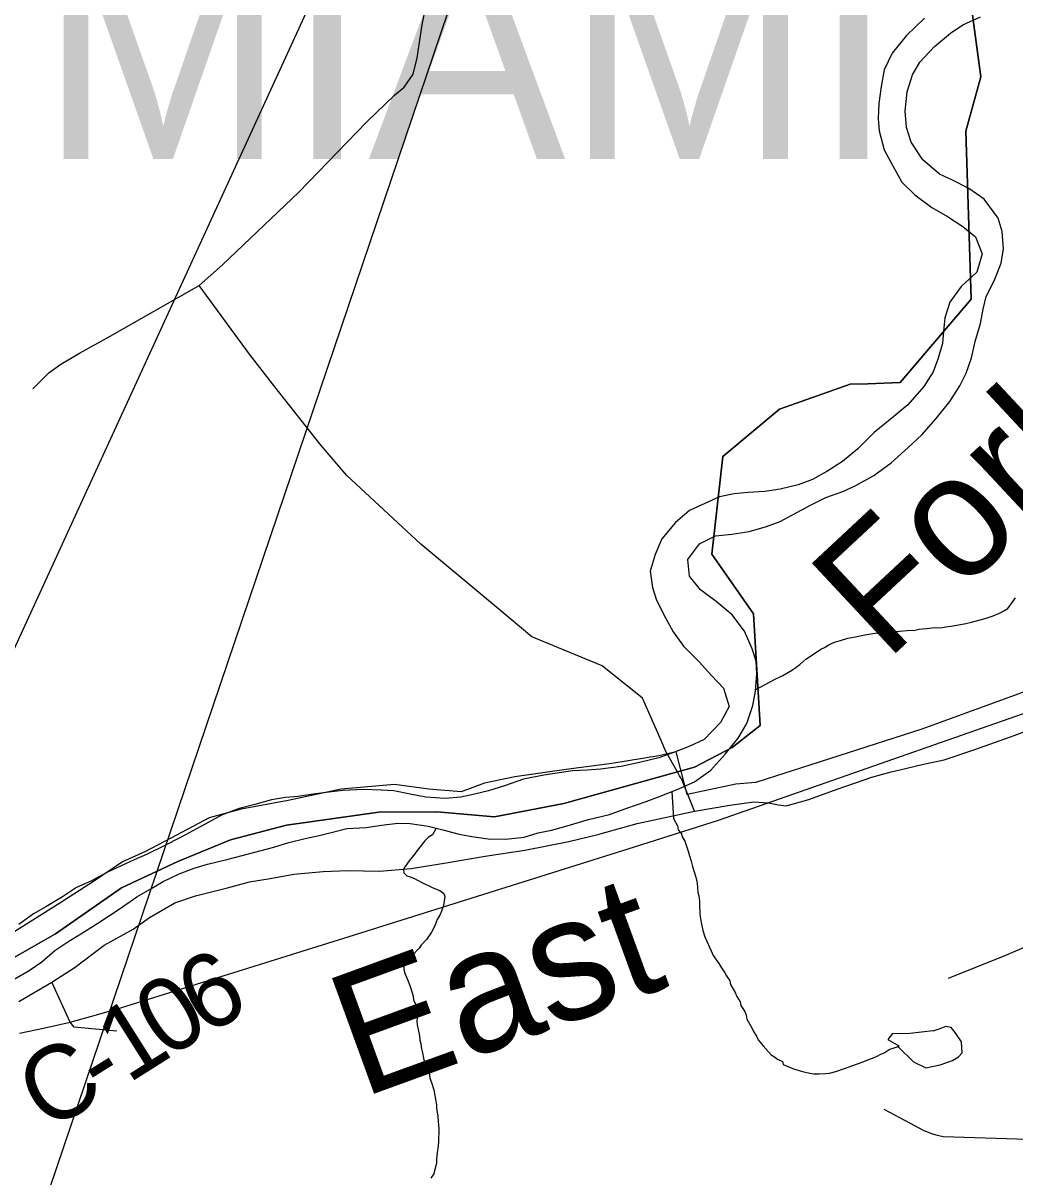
# Model space of a CAD drawing. Extents: x 44.2 to 78.2, y 4.5 to 26.5.
# Drawn here: x 49.072 to 49.836, y 20.266 to 21.155 of the extents above; entities that cross this region are included whole.
import ezdxf

# ---------------------------------------------------------------- set-up
doc = ezdxf.new("R2010")
doc.units = 0
for name, color, linetype in [('GM_X_City_Street', 7, 'Continuous'), ('GM_X_Corporation', 7, 'Continuous'), ('GM_X_County_Road', 7, 'Continuous'), ('GM_X_County_Road_Text', 7, 'Continuous'), ('GM_X_Major_River', 7, 'Continuous'), ('GM_X_Major_River_Text', 7, 'Continuous'), ('GM_X_Minor_Lake', 7, 'Continuous'), ('GM_X_Minor_River', 7, 'Continuous'), ('GM_X_Rail_Line', 7, 'Continuous'), ('GM_X_Township_Road', 7, 'Continuous'), ('GM_X_Township_Text', 7, 'Continuous'), ('SH_Data', 7, 'Continuous')]:
    doc.layers.add(name, color=color, linetype=linetype)

msp = doc.modelspace()

# ---------------------------------------------------------------- linework, layer by layer
at = {"layer": 'GM_X_City_Street'}
msp.add_lwpolyline([(49.07968, 20.87319), (49.09182, 20.88533), (49.10127, 20.89208), (49.11557, 20.90071), (49.13904, 20.91366), (49.20768, 20.95273)], dxfattribs=at)
at = {"layer": 'GM_X_Corporation'}
msp.add_lwpolyline([(49.89099, 20.65721), (49.76414, 20.61103), (49.63643, 20.56998), (49.62086, 20.56872), (49.58355, 20.56061), (49.57505, 20.59345), (49.56153, 20.59035), (49.52539, 20.58465), (49.49021, 20.57989), (49.45074, 20.57428), (49.42744, 20.56943), (49.40936, 20.56277), (49.38464, 20.56467), (49.358, 20.56847), (49.31711, 20.56467), (49.27621, 20.55611), (49.24007, 20.54945), (49.21534, 20.54279), (49.19023, 20.52931), (49.16636, 20.51686), (49.14877, 20.50878), (49.12642, 20.49355), (49.10027, 20.47691), (49.05889, 20.45075)], dxfattribs=at)
at = {"layer": 'GM_X_County_Road'}
for points in [[(49.43689, 20.70467), (49.37826, 20.75352), (49.32135, 20.80634), (49.30173, 20.82953), (49.2659, 20.87471), (49.24633, 20.89981), (49.20768, 20.95273), (49.22569, 20.96854), (49.28439, 21.02463), (49.33646, 21.07856), (49.35812, 21.09941), (49.36563, 21.10533), (49.37237, 21.1155), (49.37567, 21.12815), (49.37938, 21.15358), (49.38172, 21.16499)], [(49.56364, 20.60177), (49.54905, 20.63486), (49.51808, 20.6598), (49.46389, 20.68217), (49.43689, 20.70467)], [(49.58911, 20.54782), (49.61631, 20.5525), (49.63484, 20.55506), (49.64603, 20.55435), (49.6539, 20.55263), (49.65972, 20.55195), (49.67719, 20.55691), (49.69894, 20.56479), (49.72565, 20.57404), (49.74055, 20.57815), (49.75151, 20.58072), (49.76555, 20.58397), (49.78131, 20.5874), (49.80494, 20.59527), (49.83524, 20.60623), (49.89398, 20.62815)], [(49.57768, 20.57515), (49.57631, 20.57761), (49.56688, 20.59441), (49.56364, 20.60177)], [(49.58911, 20.54782), (49.57906, 20.5727), (49.57768, 20.57515)], [(49.06883, 20.40132), (49.09413, 20.41614), (49.1122, 20.4277), (49.13444, 20.44465), (49.15684, 20.45698), (49.16948, 20.46601), (49.189, 20.47722), (49.2049, 20.48264), (49.22948, 20.48878), (49.24646, 20.49348), (49.26237, 20.49601), (49.2805, 20.49926), (49.30328, 20.50146), (49.32185, 20.50223), (49.34664, 20.5016), (49.37096, 20.50363), (49.39799, 20.50796), (49.42801, 20.51309), (49.45856, 20.51774), (49.49238, 20.52439), (49.51475, 20.52998), (49.54492, 20.53829), (49.58911, 20.54782)]]:
    msp.add_lwpolyline(points, dxfattribs=at)
at = {"layer": 'GM_X_Major_River'}
for points in [[(49.80527, 20.90944), (49.80937, 20.92343), (49.81151, 20.93441), (49.81362, 20.94426), (49.81996, 20.9563), (49.82519, 20.96988), (49.82695, 20.98088), (49.8261, 20.9942), (49.82291, 21.00454), (49.81223, 21.01921), (49.80026, 21.02744), (49.78787, 21.03378), (49.77772, 21.03856), (49.76505, 21.04947), (49.75586, 21.06297), (49.75231, 21.07445), (49.75145, 21.08702), (49.75291, 21.10182), (49.757, 21.11505), (49.76253, 21.12482), (49.7738, 21.13676), (49.78617, 21.14715), (49.7958, 21.15342), (49.80922, 21.15961)], [(49.7663, 21.15859), (49.75234, 21.14519), (49.74142, 21.13172), (49.73506, 21.11892), (49.73288, 21.10603), (49.73108, 21.09276), (49.73045, 21.08136), (49.73138, 21.07184), (49.73524, 21.05731), (49.74034, 21.04769), (49.74874, 21.03231), (49.75877, 21.02259), (49.77185, 21.01282), (49.78384, 21.00572), (49.79582, 20.99825), (49.80551, 20.99006), (49.81054, 20.97703), (49.80644, 20.96304), (49.79443, 20.95188), (49.78581, 20.93989), (49.78175, 20.9278), (49.78077, 20.91755), (49.78018, 20.90805), (49.7765, 20.89596), (49.77287, 20.88614), (49.76579, 20.87488), (49.75333, 20.86068), (49.74251, 20.85178), (49.72743, 20.83954), (49.71501, 20.82686), (49.70303, 20.81722), (49.69109, 20.80948), (49.67995, 20.80324), (49.66885, 20.79929), (49.65511, 20.79577), (49.6433, 20.79411), (49.63038, 20.79323), (49.61973, 20.79231), (49.60828, 20.78988), (49.59716, 20.78479), (49.58528, 20.77933), (49.57444, 20.77004), (49.56392, 20.75771), (49.55872, 20.74564), (49.55503, 20.73279), (49.55665, 20.7202), (49.55985, 20.71025), (49.56677, 20.69679), (49.5726, 20.68603), (49.58071, 20.67483), (49.5926, 20.66279), (49.60224, 20.65233), (49.61152, 20.64263), (49.61576, 20.62846), (49.60903, 20.61605), (49.5966, 20.603), (49.58548, 20.5979), (49.57361, 20.5932), (49.56175, 20.58888), (49.54686, 20.58538), (49.53275, 20.58225), (49.51676, 20.5803), (49.50649, 20.57937), (49.49509, 20.57884), (49.473, 20.57549)], [(49.06527, 20.41843), (49.0768, 20.42504), (49.08644, 20.43169), (49.0965, 20.44061), (49.10652, 20.44725), (49.11998, 20.45534), (49.12961, 20.46161), (49.14617, 20.4723), (49.15966, 20.48191), (49.17004, 20.48778), (49.18004, 20.49366), (49.19232, 20.49949), (49.2038, 20.50382), (49.21412, 20.50703), (49.229, 20.51053), (49.24084, 20.51371), (49.26527, 20.52005), (49.27674, 20.52362), (49.28934, 20.52678), (49.30002, 20.52923), (49.31032, 20.53168), (49.3214, 20.53449), (49.33622, 20.53533), (49.34802, 20.53699), (49.36059, 20.53863), (49.37007, 20.53843), (49.38407, 20.53625), (49.39539, 20.53335), (49.40785, 20.53005), (49.41768, 20.52833), (49.43017, 20.52655), (49.44345, 20.52628), (49.45791, 20.52788), (49.46861, 20.53108), (49.47891, 20.53315), (49.48922, 20.53598), (49.50756, 20.54131), (49.52359, 20.54517), (49.53698, 20.55021), (49.5519, 20.55523), (49.56147, 20.55884), (49.57564, 20.56464), (49.58905, 20.57044), (49.60178, 20.57931), (49.61268, 20.59164), (49.62282, 20.60398), (49.62952, 20.61525), (49.634, 20.62923), (49.63614, 20.64022), (49.63719, 20.65351), (49.63664, 20.66341), (49.63344, 20.67298), (49.62766, 20.68641), (49.61807, 20.69916), (49.60576, 20.7093), (49.59381, 20.7183), (49.58531, 20.72874), (49.58407, 20.7417), (49.59307, 20.75368), (49.60535, 20.7599), (49.61791, 20.76116), (49.63124, 20.76317), (49.64461, 20.76708), (49.65495, 20.77105), (49.66455, 20.77618), (49.67838, 20.7835), (49.69027, 20.78934), (49.70328, 20.79401), (49.71287, 20.79838), (49.72709, 20.80646), (49.74059, 20.81607), (49.75375, 20.82797), (49.76422, 20.83764), (49.77512, 20.85035), (49.78566, 20.86344), (49.79351, 20.87545), (49.79828, 20.88524), (49.80234, 20.89695), (49.80527, 20.90944)], [(49.473, 20.57549), (49.45737, 20.57239), (49.44283, 20.56737), (49.4306, 20.56343), (49.41877, 20.56063), (49.40924, 20.55855), (49.39707, 20.55766), (49.38228, 20.55872), (49.37018, 20.56087), (49.35771, 20.56341), (49.34785, 20.564), (49.3342, 20.56466), (49.31824, 20.56384), (49.30758, 20.56254), (49.2954, 20.56089), (49.28397, 20.55922), (49.27408, 20.55828), (49.26342, 20.5566), (49.25043, 20.55307), (49.23859, 20.54989), (49.22482, 20.54485), (49.21521, 20.53934), (49.20292, 20.53275), (49.19331, 20.52762), (49.18064, 20.52103), (49.1676, 20.51483), (49.15763, 20.51047), (49.14766, 20.50574), (49.13654, 20.50064), (49.12425, 20.49404), (49.11313, 20.48895), (49.10234, 20.48194), (49.08965, 20.47422), (49.08004, 20.46871), (49.06885, 20.46057)]]:
    msp.add_lwpolyline(points, dxfattribs=at)
at = {"layer": 'GM_X_Minor_Lake'}
msp.add_lwpolyline([(49.74652, 20.36718), (49.74628, 20.36614), (49.75782, 20.35488), (49.76723, 20.35013), (49.77829, 20.35256), (49.78786, 20.35578), (49.79248, 20.35873), (49.7952, 20.36171), (49.79461, 20.37008), (49.78983, 20.3774), (49.78687, 20.38126), (49.78271, 20.38211), (49.77734, 20.37994), (49.77275, 20.37851)], dxfattribs=at)
at = {"layer": 'GM_X_Minor_River'}
for points in [[(49.63624, 20.64153), (49.6506, 20.64917), (49.65713, 20.65241), (49.66446, 20.65677), (49.67026, 20.66079), (49.67492, 20.66484), (49.67994, 20.66813), (49.68651, 20.67251), (49.68921, 20.67396), (49.69192, 20.67578), (49.6946, 20.67685), (49.69768, 20.67828), (49.7015, 20.67932), (49.70724, 20.68107), (49.71296, 20.68206), (49.72022, 20.68377), (49.72633, 20.68475), (49.73204, 20.68535), (49.73433, 20.68568), (49.74118, 20.68625), (49.74688, 20.68648), (49.75297, 20.68708), (49.75868, 20.68731), (49.76211, 20.68798), (49.76478, 20.68829), (49.7682, 20.68858), (49.77392, 20.68919), (49.77657, 20.68912), (49.78, 20.68941), (49.78267, 20.68972), (49.78648, 20.69038), (49.79106, 20.69102), (49.79793, 20.69236), (49.80251, 20.69338), (49.80519, 20.69407), (49.80901, 20.6951), (49.8136, 20.6965), (49.81897, 20.69826), (49.82396, 20.7004), (49.82742, 20.70221), (49.83051, 20.70403), (49.83247, 20.70663), (49.83641, 20.71222)], [(49.57166, 20.56301), (49.57306, 20.54231), (49.57595, 20.53654), (49.57663, 20.53349), (49.57921, 20.53039), (49.57953, 20.5281), (49.58172, 20.52463), (49.58312, 20.52004), (49.58419, 20.51698), (49.58524, 20.51353), (49.58665, 20.50932), (49.58768, 20.50512), (49.59014, 20.49709), (49.59116, 20.49251), (49.59174, 20.48529), (49.59243, 20.48261), (49.59308, 20.47842), (49.593, 20.47539), (49.59323, 20.46932), (49.59354, 20.46665), (49.59419, 20.46208), (49.59555, 20.45598), (49.59694, 20.45101), (49.60199, 20.44025), (49.60342, 20.4368), (49.60782, 20.43061), (49.60927, 20.42792), (49.61257, 20.42328), (49.61365, 20.42098), (49.61621, 20.41712), (49.6169, 20.41444), (49.62054, 20.40828), (49.6216, 20.40521), (49.62416, 20.40097), (49.62485, 20.3983), (49.62777, 20.39367), (49.62883, 20.39061), (49.62951, 20.38755), (49.63314, 20.38101), (49.63422, 20.37871), (49.63715, 20.37407), (49.63823, 20.37177), (49.64191, 20.36712), (49.64597, 20.36246), (49.64819, 20.36013), (49.65081, 20.35854), (49.65304, 20.35697), (49.65679, 20.35497), (49.65749, 20.35268), (49.6605, 20.35146), (49.66538, 20.34943), (49.67217, 20.34736), (49.67783, 20.34607), (49.68086, 20.34561), (49.68504, 20.34551), (49.69036, 20.34575), (49.69303, 20.34606), (49.698, 20.34744), (49.70451, 20.34955), (49.71831, 20.3545), (49.72253, 20.35629), (49.72752, 20.35805), (49.72982, 20.35913), (49.73252, 20.36058), (49.7352, 20.36165), (49.73907, 20.3642), (49.7452, 20.36632), (49.74652, 20.36718)], [(49.39019, 20.53468), (49.38738, 20.52971), (49.3843, 20.52789), (49.38156, 20.52493), (49.37568, 20.5175), (49.37371, 20.51489), (49.3694, 20.50969), (49.36625, 20.50522), (49.36505, 20.50298), (49.36536, 20.50031), (49.36758, 20.49798), (49.37022, 20.49715), (49.37361, 20.49592), (49.37586, 20.49473), (49.3796, 20.49273), (49.38486, 20.49032), (49.38711, 20.48912), (49.39312, 20.48669), (49.3961, 20.48433), (49.39681, 20.48204), (49.39587, 20.47523), (49.39424, 20.47072), (49.39302, 20.46772), (49.39104, 20.46436), (49.38941, 20.46023), (49.38821, 20.4576), (49.38661, 20.45461), (49.38267, 20.44902), (49.37876, 20.44457), (49.37718, 20.44233), (49.37173, 20.43679), (49.36859, 20.43307), (49.36662, 20.43009), (49.36504, 20.42785), (49.3657, 20.42367), (49.36822, 20.41829), (49.37, 20.41369), (49.3707, 20.41139), (49.37244, 20.40528), (49.37276, 20.40261), (49.37419, 20.39916), (49.37445, 20.3946), (49.37476, 20.39194), (49.37545, 20.38889), (49.37537, 20.38585), (49.37568, 20.38319), (49.37635, 20.37976), (49.37737, 20.3748), (49.37766, 20.37138), (49.37835, 20.3687), (49.37901, 20.36489), (49.3797, 20.36184), (49.38035, 20.35765), (49.38105, 20.35535), (49.38355, 20.34921), (49.38497, 20.34501), (49.38528, 20.34234), (49.38671, 20.33889), (49.38846, 20.33315), (49.38911, 20.32896), (49.39045, 20.32172), (49.39038, 20.31907), (49.39136, 20.31259), (49.39164, 20.30879), (49.39226, 20.30308), (49.39199, 20.29285), (49.39149, 20.28793), (49.39103, 20.2849), (49.39052, 20.2796), (49.39045, 20.27695), (49.38961, 20.27356), (49.38878, 20.27092), (49.38834, 20.26866), (49.38598, 20.26531)], [(49.77287, 20.37855), (49.75486, 20.3766), (49.74725, 20.37638), (49.74156, 20.3765), (49.73804, 20.37201), (49.74652, 20.36718)]]:
    msp.add_lwpolyline(points, dxfattribs=at)
at = {"layer": 'GM_X_Rail_Line'}
for points in [[(49.05006, 20.42655), (49.09709, 20.45325), (49.14794, 20.48884), (49.19115, 20.50919), (49.23183, 20.52572), (49.27504, 20.53716), (49.3461, 20.54699), (49.39071, 20.54733), (49.4352, 20.54351), (49.48858, 20.55368), (49.57607, 20.57813), (49.589, 20.58165), (49.61824, 20.59691), (49.6398, 20.61391), (49.63459, 20.69971), (49.60243, 20.74586), (49.611, 20.82094), (49.65451, 20.85743), (49.7091, 20.87663), (49.72257, 20.87707), (49.74742, 20.87787), (49.80206, 20.94229), (49.79795, 21.07153), (49.80971, 21.1135), (49.80302, 21.16301)], [(49.80302, 21.16301), (49.80971, 21.1135), (49.79795, 21.07153), (49.80206, 20.94229), (49.74742, 20.87787), (49.72257, 20.87707), (49.7091, 20.87663), (49.65451, 20.85743), (49.611, 20.82094), (49.60243, 20.74586), (49.63459, 20.69971), (49.6398, 20.61391), (49.61824, 20.59691), (49.589, 20.58165), (49.57607, 20.57813), (49.48858, 20.55368), (49.4352, 20.54351), (49.39071, 20.54733), (49.3461, 20.54699), (49.27504, 20.53716), (49.23183, 20.52572), (49.19115, 20.50919), (49.14794, 20.48884), (49.09709, 20.45325), (49.05006, 20.42655)], [(49.06921, 20.37698), (49.08777, 20.38063), (49.10823, 20.38539), (49.12393, 20.38967), (49.14471, 20.3957), (49.32311, 20.45136), (49.54299, 20.5203), (49.60769, 20.54082), (49.9144, 20.64833)]]:
    msp.add_lwpolyline(points, dxfattribs=at)
at = {"layer": 'GM_X_Township_Road'}
for points in [[(49.84474, 20.44367), (49.82854, 20.43677), (49.78432, 20.41886)], [(49.1444, 20.37839), (49.11137, 20.38157), (49.10827, 20.38529), (49.09413, 20.41614)], [(49.73483, 20.3183), (49.75513, 20.30765), (49.76528, 20.30208), (49.77072, 20.29998), (49.77505, 20.29862), (49.78062, 20.29738), (49.84561, 20.29515), (49.89351, 20.29383), (49.91195, 20.29314)]]:
    msp.add_lwpolyline(points, dxfattribs=at)
at = {"layer": 'SH_Data'}
msp.add_lwpolyline([(49.00464, 20.54121), (49.70559, 22.06866), (49.00464, 19.99878)], close=True, dxfattribs=at)

# ---------------------------------------------------------------- texts
at = {"layer": 'GM_X_County_Road_Text'}
for s, rotation, p in [('6', 28.00575, (49.21114, 20.37461)), ('0', 32.51667, (49.18264, 20.35639)), ('1', 32.26395, (49.15282, 20.33756)), ('C', 29.17894, (49.08943, 20.30071)), ('-', 32.07175, (49.13287, 20.32506))]:
    msp.add_text(s, height=0.05682, rotation=rotation, dxfattribs=at).set_placement(p)
at = {"layer": 'GM_X_Major_River_Text'}
for s, height, rotation, p in [('Fork', 0.094704, 43.00312, (49.73653, 20.66248)), ('East', 0.0947, 20.00344, (49.33265, 20.32665))]:
    msp.add_text(s, height=height, rotation=rotation, dxfattribs=at).set_placement(p)
at = {"layer": 'GM_X_Township_Text'}
msp.add_text('MIAMI', height=0.170455, rotation=0.00001, dxfattribs=at).set_placement((49.08471, 21.05001))

doc.saveas('drawing.dxf')
